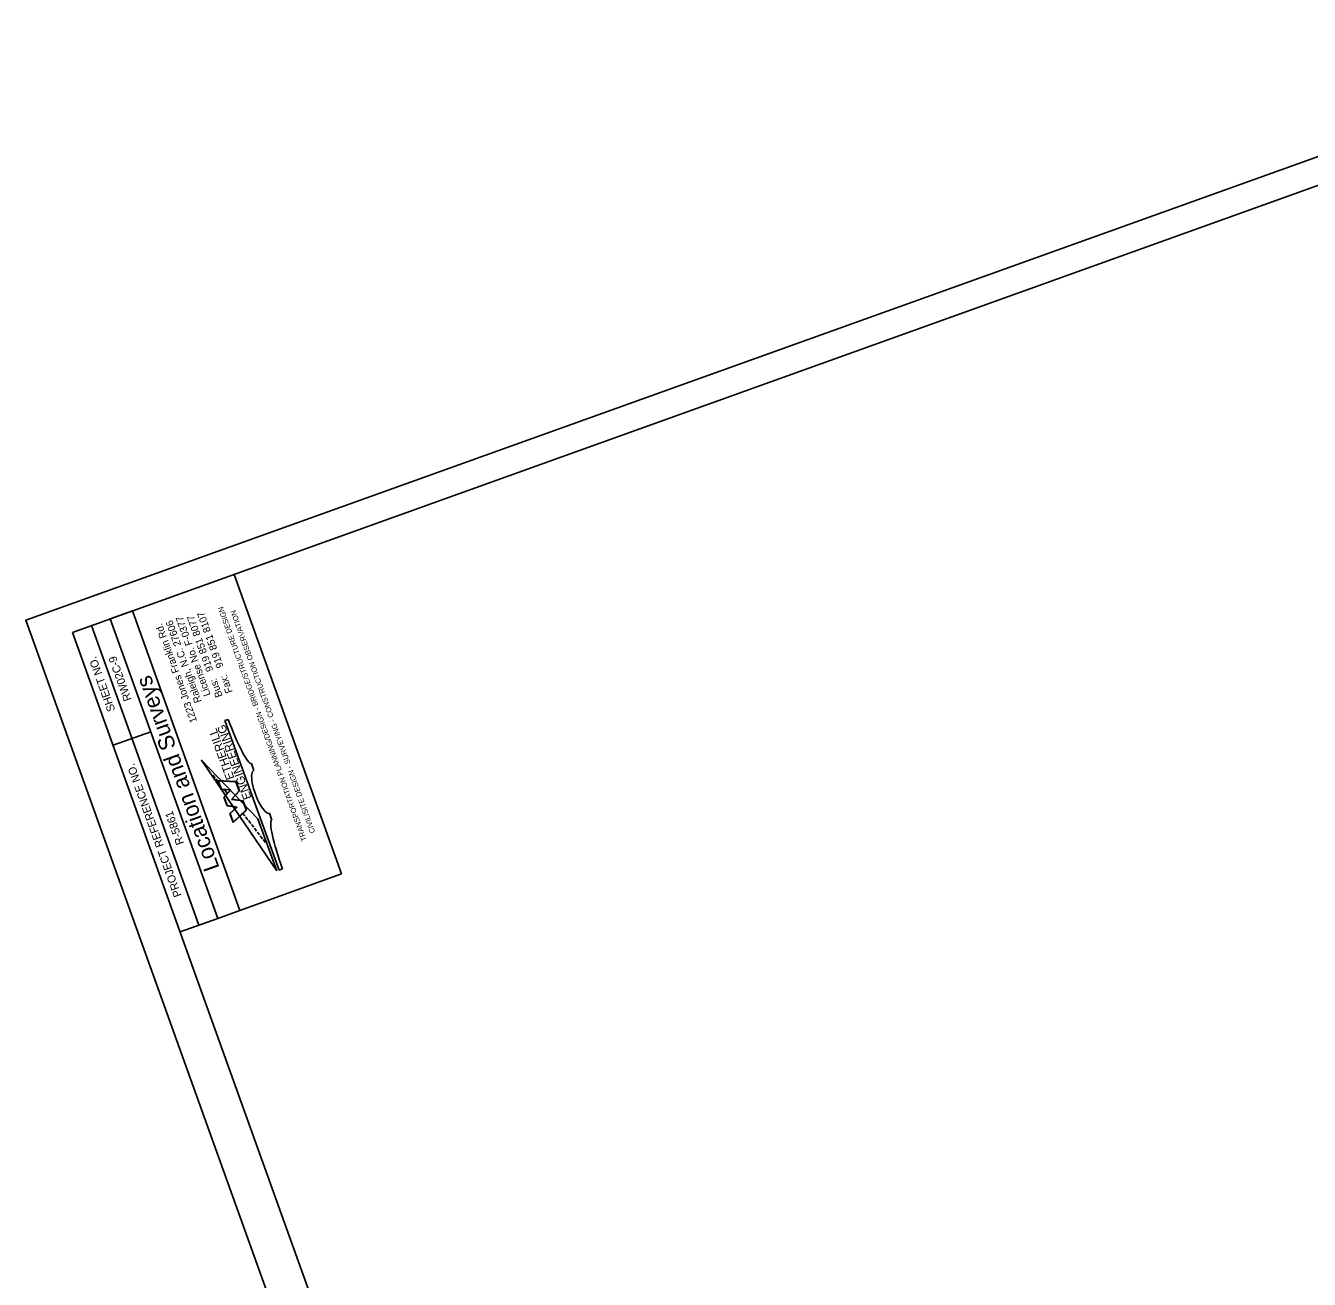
# Model space of a CAD drawing. Extents: x 471172 to 474725, y 509605 to 513938.
# Drawn here: x 471172 to 472949, y 512203 to 513938 of the extents above; entities that cross this region are included whole.
import ezdxf

# ---------------------------------------------------------------- set-up
doc = ezdxf.new("R2010")
doc.units = 0
for name, color, linetype in [('CTL Sheet Border CELL', 7, 'Continuous'), ('CTL Sheet Notes CELL', 7, 'Continuous'), ('Sheet Plot Border Outside CELL', 7, 'Continuous')]:
    doc.layers.add(name, color=color, linetype=linetype)

msp = doc.modelspace()

# ---------------------------------------------------------------- linework, layer by layer
at = {"layer": 'CTL Sheet Border CELL'}
for p, q in [((471609.5, 512764), (471460.7, 513178.7)), ((471172.4, 513115.2), (471172.4, 513115.2)), ((471222.5, 513122.6), (471222.5, 513122.6)), ((471222.5, 513122.6), (471222.5, 513122.6)), ((471412.2, 512693.2), (471263.3, 513107.9)), ((471293.4, 512942.2), (471345.5, 512960.9)), ((471468.9, 512713.6), (471609.5, 512764.1)), ((471386.2, 512683.9), (471438.3, 512702.6))]:
    msp.add_line(p, q, dxfattribs=at)
for points in [[(471237.2, 513098.5), (472359.8, 509971.9), (474548.4, 510757.7), (473425.8, 513884.3)], [(471438.3, 512702.6), (471289.4, 513117.2), (471320.1, 513128.2), (471468.9, 512713.6)]]:
    msp.add_lwpolyline(points, close=True, dxfattribs=at)
at = {"layer": 'CTL Sheet Notes CELL'}
for p, q in [((471452.8, 512978.1), (471448.1, 512976.4)), ((471448.1, 512976.4), (471523, 512769.5)), ((471488.1, 512907.5), (471484.7, 512916.9)), ((471434.6, 512897.1), (471431.5, 512901)), ((471438.7, 512891.8), (471435.6, 512895.8)), ((471438.5, 512893.4), (471443, 512881)), ((471463.4, 512891.7), (471438.9, 512893.1)), ((471438.9, 512893.1), (471443.2, 512881.3)), ((471443, 512881), (471455.7, 512880.3)), ((471443.2, 512881.3), (471456.5, 512880.6)), ((471455.7, 512880.3), (471446.8, 512870.4)), ((471456.5, 512880.6), (471447.2, 512870.4)), ((471451, 512876), (471447.9, 512880)), ((471457.1, 512867.3), (471467.9, 512879.2)), ((471457.8, 512867.6), (471468.3, 512879.1)), ((471467.9, 512879.2), (471463.4, 512891.7)), ((471468.3, 512879.1), (471463.6, 512892)), ((471446.8, 512870.4), (471451.2, 512858.3)), ((471447.2, 512870.4), (471451.4, 512858.6)), ((471451.2, 512858.3), (471464.4, 512856.4)), ((471451.4, 512858.6), (471465.1, 512856.7)), ((471473, 512865.1), (471457.1, 512867.3)), ((471473.3, 512865.4), (471457.8, 512867.6)), ((471477.6, 512852.6), (471473, 512865.1)), ((471477.9, 512852.5), (471473.3, 512865.4)), ((471464.4, 512856.4), (471455, 512847.7)), ((471455, 512847.7), (471459.5, 512835.3)), ((471465.1, 512856.7), (471455.4, 512847.6)), ((471455.4, 512847.6), (471459.7, 512835.9)), ((471459.5, 512835.3), (471477.9, 512852.5)), ((471459.7, 512835.9), (471477.6, 512852.6)), ((471475.6, 512844.5), (471472.5, 512848.4)), ((471479.7, 512839.2), (471476.6, 512843.2)), ((471513.1, 512838.6), (471509.7, 512848)), ((471483.8, 512834), (471480.7, 512837.9)), ((471487.9, 512828.7), (471484.8, 512832.7)), ((471492, 512823.5), (471488.9, 512827.4)), ((471496.1, 512818.2), (471493, 512822.1)), ((471500.2, 512812.9), (471497.1, 512816.9)), ((471504.3, 512807.7), (471501.2, 512811.6)), ((471523, 512769.5), (471527.7, 512771.2))]:
    msp.add_line(p, q, dxfattribs=at)
msp.add_lwpolyline([(471519.9, 512768.4), (471493.8, 512840.5), (471415.6, 512921.4)], close=True, dxfattribs=at)
msp.add_lwpolyline([(471463.6, 512892), (471463.2, 512892.1), (471438.5, 512893.4)], dxfattribs=at)
for centre, major_axis, ratio, start_param, end_param in [((471461.4, 512981.2), (-23.3, 64.2), 0.134146, 1.570796, 3.141593), ((471498.9, 512877.8), (-10.8, 29.8), 0.289474, 0, 3.141593), ((471536.3, 512774.3), (23.3, -64.2), 0.134146, 3.141593, 4.712389)]:
    msp.add_ellipse(centre, major_axis=major_axis, ratio=ratio, start_param=start_param, end_param=end_param, dxfattribs=at)
at = {"layer": 'Sheet Plot Border Outside CELL'}
msp.add_lwpolyline([(474725.5, 510428.3), (473465.2, 513938.4), (471172.4, 513115.2), (472432.7, 509605.1)], close=True, dxfattribs=at)

# ---------------------------------------------------------------- texts
at = {"layer": 'CTL Sheet Border CELL'}
for s, height, p in [('SHEET NO.', 11.07, (471296.5, 512991.1)), ('RW02C-9', 11.07, (471319.1, 513005.6)), ('Location and Surveys', 22.147, (471441, 512772.6)), ('PROJECT REFERENCE NO.', 11.074, (471388.4, 512734.3)), ('R-5861', 11.07, (471391.6, 512806.6))]:
    msp.add_text(s, height=height, rotation=109.7508, dxfattribs=at).set_placement(p)
at = {"layer": 'CTL Sheet Notes CELL'}
for s, height, rotation, p in [('Fax:   919 851 8107', 10, 109.7508, (471458.9, 513016.2)), ('TRANSPORTATION PLANNING/DESIGN - BRIDGE/STRUCTURE DESIGN', 7.333, 109.7508, (471561.6, 512810.9)), ('1223 Jones Franklin Rd. ', 10, 109.7508, (471409.8, 512975.4)), ('Raleigh, N.C. 27606', 10, 109.7508, (471415.9, 513002.9)), ('License No. F-0377', 10, 109.7508, (471428.5, 513012.1)), ('Bus:   919 851 8077', 10, 109.7508, (471445, 513010.5)), ('CIVIL/SITE DESIGN - SURVEYING - CONSTRUCTION OBSERVATION', 7.333, 109.7508, (471573.2, 512821.9)), ('ETHERILL', 11.67, 109.9099, (471461.4, 512896.9)), ('ENGINEERING', 11.667, 109.9099, (471485.1, 512869.4))]:
    msp.add_text(s, height=height, rotation=rotation, dxfattribs=at).set_placement(p)

doc.saveas('drawing.dxf')
